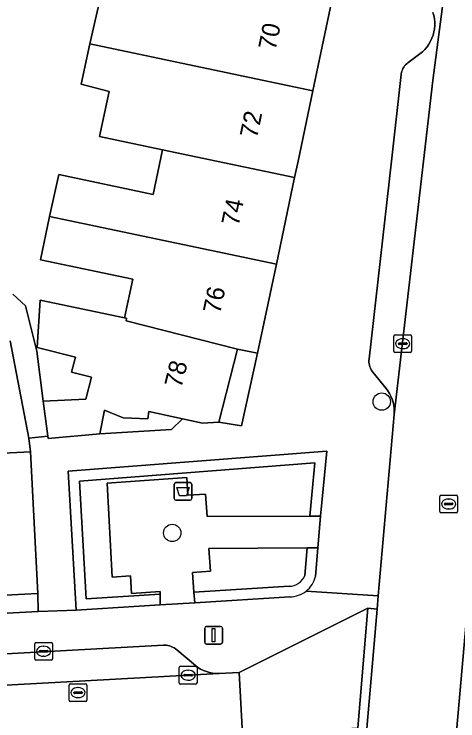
# Model space of a CAD drawing. Extents: x 160856 to 161310, y 384024 to 384878.
# Drawn here: x 161108.27 to 161133.27, y 384718.5 to 384758.27 of the extents above; entities that cross this region are included whole.
import ezdxf

# ---------------------------------------------------------------- set-up
doc = ezdxf.new("R2010")
doc.units = 0
for name, color, linetype in [('IMGEO_Afvalbak', 7, 'Continuous'), ('IMGEO_Boom', 7, 'Continuous'), ('IMGEO_Brandkraan', 7, 'Continuous'), ('IMGEO_Erf', 7, 'Continuous'), ('IMGEO_Groenvoorziening', 7, 'Continuous'), ('IMGEO_Haag', 7, 'Continuous'), ('IMGEO_Kolk', 7, 'Continuous'), ('IMGEO_Lichtmast', 7, 'Continuous'), ('IMGEO_Pand', 7, 'Continuous'), ('IMGEO_Pand_nummerreeks', 7, 'Continuous'), ('IMGEO_Parkeervlak_open', 7, 'Continuous'), ('IMGEO_Rijbaan_lokaal_open', 7, 'Continuous'), ('IMGEO_Rioolput', 7, 'Continuous'), ('IMGEO_Voetpad_open', 7, 'Continuous')]:
    doc.layers.add(name, color=color, linetype=linetype)

msp = doc.modelspace()

# ---------------------------------------------------------------- linework, layer by layer
at = {"layer": 'IMGEO_Afvalbak'}
for p, q in [((161117.389, 384731.914), (161118.179, 384731.914)), ((161118.179, 384731.914), (161117.389, 384731.914)), ((161117.289, 384731.014), (161117.289, 384731.814)), ((161117.289, 384731.814), (161117.289, 384731.014)), ((161118.279, 384731.814), (161118.279, 384731.014)), ((161118.279, 384731.014), (161118.279, 384731.814)), ((161118.179, 384730.914), (161117.389, 384730.914)), ((161117.389, 384730.914), (161118.179, 384730.914))]:
    msp.add_line(p, q, dxfattribs=at)
msp.add_lwpolyline([(161117.432, 384731.628), (161118.136, 384731.628), (161117.987, 384731.158), (161117.581, 384731.158), (161117.432, 384731.628)], dxfattribs=at)
for centre, start, end in [((161117.389, 384731.814), 90, 180), ((161117.389, 384731.814), 90, 180), ((161118.179, 384731.814), 0, 90), ((161118.179, 384731.814), 360, 90), ((161117.389, 384731.014), 180, 270), ((161117.389, 384731.014), 180, 270), ((161118.179, 384731.014), 270, 0), ((161118.179, 384731.014), 270, 0)]:
    msp.add_arc(centre, 0.1, start, end, dxfattribs=at)
at = {"layer": 'IMGEO_Boom'}
for centre in [(161128.979, 384736.468), (161117.175, 384729.078)]:
    msp.add_circle(centre, 0.489, dxfattribs=at)
at = {"layer": 'IMGEO_Brandkraan'}
for p, q in [((161109.427, 384721.993), (161109.427, 384722.845)), ((161109.502, 384722.919), (161110.354, 384722.919)), ((161110.428, 384722.845), (161110.428, 384721.993)), ((161109.686, 384722.413), (161109.686, 384722.425)), ((161110.124, 384722.376), (161109.726, 384722.376)), ((161109.729, 384722.462), (161110.127, 384722.462)), ((161109.915, 384722.699), (161109.94, 384722.699)), ((161110.17, 384722.425), (161110.17, 384722.413)), ((161109.938, 384722.139), (161109.913, 384722.139)), ((161110.354, 384721.919), (161109.502, 384721.919))]:
    msp.add_line(p, q, dxfattribs=at)
for points in [[(161109.427, 384721.993), (161109.427, 384722.845)], [(161109.502, 384722.919), (161110.354, 384722.919)], [(161110.428, 384722.845), (161110.428, 384721.993)], [(161110.354, 384721.919), (161109.502, 384721.919)]]:
    msp.add_lwpolyline(points, dxfattribs=at)
for centre, radius, start, end in [((161109.504, 384722.843), 0.0765, 91.552, 178.448), ((161109.504, 384722.843), 0.0765, 91.552, 178.448), ((161110.352, 384722.843), 0.0765, 1.552, 88.448), ((161110.352, 384722.843), 0.0765, 1.552, 88.448), ((161109.726, 384722.422), 0.0403, 85.8775, 175.7526), ((161109.723, 384722.412), 0.0366, 178.938, 274.7102), ((161110.127, 384722.419), 0.043, 264.8664, 352.4533), ((161110.131, 384722.424), 0.0386, 1.7309, 96.639), ((161109.504, 384721.995), 0.0765, 181.552, 268.448), ((161109.504, 384721.995), 0.0765, 181.552, 268.448), ((161110.352, 384721.995), 0.0765, 271.552, 358.448), ((161110.352, 384721.995), 0.0765, 271.552, 358.448)]:
    msp.add_arc(centre, radius, start, end, dxfattribs=at)
for centre, major_axis, ratio, start_param, end_param in [((161109.914, 384722.419), (-0.387, 0.002), 0.722429, 4.712389, 7.853982), ((161109.939, 384722.419), (-0.39, 0.002), 0.717154, 1.570796, 4.712389)]:
    msp.add_ellipse(centre, major_axis=major_axis, ratio=ratio, start_param=start_param, end_param=end_param, dxfattribs=at)
at = {"layer": 'IMGEO_Erf'}
for points in [[(161108.204, 384742.509), (161108.91, 384741.85), (161109.547, 384739.314), (161109.913, 384736.496), (161112.313, 384736.604), (161112.629, 384737.844), (161111.507, 384738.13), (161111.719, 384738.961), (161109.56, 384739.512), (161109.731, 384742.186), (161114.492, 384741.185), (161114.95, 384743.361), (161109.757, 384744.453), (161110.268, 384746.884), (161110.792, 384749.247), (161116.104, 384748.13), (161116.632, 384750.64), (161113.088, 384751.385), (161113.622, 384753.927), (161112.04, 384754.333), (161112.544, 384756.594), (161113.097, 384759.079)], [(161104.193, 384733.394), (161109.186, 384733.651), (161109.099, 384734.403), (161108.056, 384739.886)]]:
    msp.add_lwpolyline(points, dxfattribs=at)
for points in [[(161117.139, 384734.904), (161117.758, 384735.497), (161115.862, 384735.903), (161115.798, 384735.497), (161114.414, 384735.547), (161113.36, 384735.992), (161113.104, 384734.661)], [(161109.597, 384725.668), (161104.46, 384725.404), (161099.443, 384725.146), (161094.427, 384724.888), (161089.411, 384724.63), (161084.394, 384724.371), (161079.378, 384724.113), (161074.362, 384723.855), (161069.224, 384723.591), (161069.34, 384722.503), (161109.616, 384724.666)]]:
    msp.add_lwpolyline(points, close=True, dxfattribs=at)
at = {"layer": 'IMGEO_Groenvoorziening'}
for points in [[(161116.498, 384725.626), (161112.335, 384725.367), (161111.949, 384732), (161125.216, 384733.021), (161124.926, 384730.028), (161125.529, 384730.031), (161125.882, 384733.674), (161111.316, 384732.553), (161111.771, 384724.731), (161116.502, 384725.026)], [(161124.926, 384730.028), (161125.216, 384733.021), (161111.949, 384732), (161112.335, 384725.367), (161116.498, 384725.626), (161116.496, 384725.789), (161114.875, 384725.669), (161114.825, 384726.663), (161113.792, 384726.598), (161113.506, 384731.882), (161118, 384732.196), (161118.057, 384731.201), (161119.044, 384731.264), (161119.139, 384730)]]:
    msp.add_lwpolyline(points, close=True, dxfattribs=at)
for points in [[(161124.646, 384726.684), (161124.777, 384728.232), (161119.241, 384728.195), (161119.325, 384726.929), (161118.319, 384726.849), (161118.403, 384725.745), (161123.764, 384726.079)], [(161125.244, 384726.633), (161125.379, 384728.236), (161124.777, 384728.232), (161124.646, 384726.684)], [(161123.764, 384726.079), (161118.403, 384725.745), (161118.448, 384725.147), (161123.801, 384725.48)]]:
    msp.add_lwpolyline(points, dxfattribs=at)
for centre, radius, start, end in [((161123.771, 384727.014), 0.935, 269.5774, 339.3182), ((161123.771, 384727.014), 0.935, 269.5774, 339.3182), ((161123.789, 384726.977), 1.496, 308.5687, 346.6868), ((161123.784, 384726.982), 1.502, 270.6515, 308.593)]:
    msp.add_arc(centre, radius, start, end, dxfattribs=at)
at = {"layer": 'IMGEO_Haag'}
msp.add_lwpolyline([(161116.498, 384725.626), (161112.335, 384725.367), (161111.949, 384732), (161125.216, 384733.021), (161124.926, 384730.028), (161125.529, 384730.031), (161125.882, 384733.674), (161111.316, 384732.553), (161111.771, 384724.731), (161116.502, 384725.026)], close=True, dxfattribs=at)
for points in [[(161125.244, 384726.633), (161125.379, 384728.236), (161124.777, 384728.232), (161124.646, 384726.684)], [(161123.764, 384726.079), (161118.403, 384725.745), (161118.448, 384725.147), (161123.801, 384725.48)]]:
    msp.add_lwpolyline(points, dxfattribs=at)
for centre, radius, start, end in [((161123.771, 384727.014), 0.935, 269.5774, 339.3182), ((161123.789, 384726.977), 1.496, 308.5687, 346.6868), ((161123.784, 384726.982), 1.502, 270.6515, 308.593)]:
    msp.add_arc(centre, radius, start, end, dxfattribs=at)
at = {"layer": 'IMGEO_Kolk'}
for p, q in [((161129.663, 384739.302), (161129.663, 384740.154)), ((161129.738, 384740.228), (161130.59, 384740.228)), ((161130.151, 384740.008), (161130.176, 384740.008)), ((161130.664, 384740.154), (161130.664, 384739.302)), ((161129.922, 384739.722), (161129.922, 384739.734)), ((161130.36, 384739.685), (161129.962, 384739.685)), ((161129.965, 384739.771), (161130.363, 384739.771)), ((161130.406, 384739.734), (161130.406, 384739.722)), ((161130.59, 384739.228), (161129.738, 384739.228)), ((161130.174, 384739.448), (161130.149, 384739.448)), ((161117.648, 384721.572), (161118.5, 384721.572)), ((161117.573, 384720.646), (161117.573, 384721.498)), ((161118.061, 384721.352), (161118.086, 384721.352)), ((161118.574, 384721.498), (161118.574, 384720.646)), ((161117.832, 384721.066), (161117.832, 384721.078)), ((161118.27, 384721.029), (161117.872, 384721.029)), ((161117.875, 384721.115), (161118.273, 384721.115)), ((161118.084, 384720.792), (161118.059, 384720.792)), ((161118.316, 384721.078), (161118.316, 384721.066)), ((161118.5, 384720.572), (161117.648, 384720.572))]:
    msp.add_line(p, q, dxfattribs=at)
for points in [[(161129.663, 384739.302), (161129.663, 384740.154)], [(161129.738, 384740.228), (161130.59, 384740.228)], [(161130.664, 384740.154), (161130.664, 384739.302)], [(161130.59, 384739.228), (161129.738, 384739.228)], [(161117.648, 384721.572), (161118.5, 384721.572)], [(161117.573, 384720.646), (161117.573, 384721.498)], [(161118.574, 384721.498), (161118.574, 384720.646)], [(161118.5, 384720.572), (161117.648, 384720.572)]]:
    msp.add_lwpolyline(points, dxfattribs=at)
for centre, radius, start, end in [((161129.74, 384740.152), 0.0765, 91.552, 178.448), ((161129.74, 384740.152), 0.0765, 91.552, 178.448), ((161130.588, 384740.152), 0.0765, 1.552, 88.448), ((161130.588, 384740.152), 0.0765, 1.552, 88.448), ((161129.962, 384739.731), 0.0403, 85.8775, 175.7526), ((161129.959, 384739.721), 0.0366, 178.938, 274.7102), ((161130.363, 384739.728), 0.043, 264.8664, 352.4533), ((161130.367, 384739.733), 0.0386, 1.7309, 96.639), ((161129.74, 384739.304), 0.0765, 181.552, 268.448), ((161129.74, 384739.304), 0.0765, 181.552, 268.448), ((161130.588, 384739.304), 0.0765, 271.552, 358.448), ((161130.588, 384739.304), 0.0765, 271.552, 358.448), ((161117.65, 384721.496), 0.0765, 91.552, 178.448), ((161117.65, 384721.496), 0.0765, 91.552, 178.448), ((161118.498, 384721.496), 0.0765, 1.552, 88.448), ((161118.498, 384721.496), 0.0765, 1.552, 88.448), ((161117.872, 384721.075), 0.0403, 85.8775, 175.7526), ((161117.869, 384721.065), 0.0366, 178.938, 274.7102), ((161118.273, 384721.072), 0.043, 264.8664, 352.4533), ((161118.277, 384721.077), 0.0386, 1.7309, 96.639), ((161117.65, 384720.648), 0.0765, 181.552, 268.448), ((161117.65, 384720.648), 0.0765, 181.552, 268.448), ((161118.498, 384720.648), 0.0765, 271.552, 358.448), ((161118.498, 384720.648), 0.0765, 271.552, 358.448)]:
    msp.add_arc(centre, radius, start, end, dxfattribs=at)
for centre, major_axis, ratio, start_param, end_param in [((161130.15, 384739.728), (-0.387, 0.002), 0.722429, 4.712389, 7.853982), ((161130.175, 384739.728), (-0.39, 0.002), 0.717154, 1.570796, 4.712389), ((161118.06, 384721.072), (-0.387, 0.002), 0.722429, 4.712389, 7.853982), ((161118.085, 384721.072), (-0.39, 0.002), 0.717154, 1.570796, 4.712389)]:
    msp.add_ellipse(centre, major_axis=major_axis, ratio=ratio, start_param=start_param, end_param=end_param, dxfattribs=at)
at = {"layer": 'IMGEO_Lichtmast'}
for p, q in [((161119.01, 384722.919), (161119.01, 384723.719)), ((161119.01, 384723.719), (161119.01, 384722.919)), ((161119.11, 384723.819), (161119.9, 384723.819)), ((161119.9, 384723.819), (161119.11, 384723.819)), ((161120, 384723.719), (161120, 384722.919)), ((161120, 384722.919), (161120, 384723.719)), ((161119.9, 384722.819), (161119.11, 384722.819)), ((161119.11, 384722.819), (161119.9, 384722.819))]:
    msp.add_line(p, q, dxfattribs=at)
msp.add_lwpolyline([(161119.43, 384723.694), (161119.58, 384723.694), (161119.58, 384722.944), (161119.43, 384722.944), (161119.43, 384723.694)], dxfattribs=at)
for centre, start, end in [((161119.11, 384723.719), 90, 180), ((161119.11, 384723.719), 90, 180), ((161119.9, 384723.719), 0, 90), ((161119.9, 384723.719), 360, 90), ((161119.11, 384722.919), 180, 270), ((161119.11, 384722.919), 180, 270), ((161119.9, 384722.919), 270, 0), ((161119.9, 384722.919), 270, 0)]:
    msp.add_arc(centre, 0.1, start, end, dxfattribs=at)
at = {"layer": 'IMGEO_Pand'}
for points in [[(161114.927, 384761.077), (161114.448, 384758.795), (161113.097, 384759.079), (161112.544, 384756.594), (161125.094, 384753.955), (161126.145, 384758.952), (161125.127, 384759.166), (161118.763, 384760.502), (161118.728, 384760.335), (161117.644, 384760.568)], [(161124.069, 384749.076), (161124.263, 384750), (161125.094, 384753.955), (161112.544, 384756.594), (161112.04, 384754.333), (161113.622, 384753.927), (161113.088, 384751.385), (161116.632, 384750.64), (161119.677, 384750)], [(161124.069, 384749.076), (161119.677, 384750), (161116.632, 384750.64), (161116.104, 384748.13), (161110.792, 384749.247), (161110.268, 384746.884), (161123.043, 384744.198)], [(161123.043, 384744.198), (161110.268, 384746.884), (161109.757, 384744.453), (161114.95, 384743.361), (161114.492, 384741.185), (161114.61, 384741.16), (161114.574, 384741.018), (161120.854, 384739.425), (161121.99, 384739.186)], [(161120.854, 384739.425), (161114.574, 384741.018), (161114.61, 384741.16), (161114.492, 384741.185), (161109.731, 384742.186), (161109.56, 384739.512), (161111.719, 384738.961), (161111.507, 384738.13), (161112.629, 384737.844), (161112.313, 384736.604), (161109.913, 384736.496), (161110.169, 384734.526), (161110.186, 384734.397), (161113.104, 384734.661), (161113.36, 384735.992), (161114.414, 384735.547), (161115.798, 384735.497), (161115.862, 384735.903), (161117.758, 384735.497), (161118.878, 384735.258), (161119.811, 384735.306)], [(161104.46, 384725.404), (161109.597, 384725.668), (161109.186, 384733.651), (161104.193, 384733.394), (161104.049, 384733.386)]]:
    msp.add_lwpolyline(points, close=True, dxfattribs=at)
at = {"layer": 'IMGEO_Parkeervlak_open'}
for points in [[(161131.858, 384758.372), (161131.91, 384758.193), (161131.945, 384758.011), (161131.964, 384757.826), (161131.966, 384757.64), (161131.951, 384757.454), (161131.921, 384757.271), (161131.873, 384757.091), (161131.81, 384756.916), (161131.732, 384756.747), (161131.639, 384756.586), (161131.532, 384756.434), (161131.411, 384756.293), (161131.279, 384756.162), (161131.135, 384756.044), (161130.45, 384755.539), (161130.385, 384755.486), (161130.324, 384755.428), (161130.269, 384755.365), (161130.22, 384755.297), (161130.178, 384755.224), (161130.142, 384755.149), (161130.112, 384755.07), (161130.09, 384754.989), (161130.075, 384754.906), (161130.073, 384754.886), (161129.521, 384750), (161128.265, 384738.873), (161128.259, 384738.783), (161128.261, 384738.693), (161128.271, 384738.603), (161128.289, 384738.515), (161128.315, 384738.428), (161128.348, 384738.345), (161128.389, 384738.264), (161128.437, 384738.188), (161128.478, 384738.132), (161129.232, 384737.201), (161129.326, 384737.078), (161129.421, 384736.931), (161129.502, 384736.775), (161129.569, 384736.613), (161129.621, 384736.445), (161129.658, 384736.274), (161129.68, 384736.1), (161129.686, 384735.924), (161129.676, 384735.749), (161131.333, 384750), (161131.86, 384754.533), (161132.507, 384759.586)], [(161134.909, 384737.229), (161132.216, 384706.852), (161132.281, 384707.27), (161132.384, 384707.682), (161132.523, 384708.084), (161132.697, 384708.472), (161132.905, 384708.842), (161133.8, 384709.628), (161133.869, 384709.695), (161133.932, 384709.768), (161133.988, 384709.846), (161134.038, 384709.929), (161134.079, 384710.016), (161134.112, 384710.106), (161134.138, 384710.199), (161134.155, 384710.293), (161134.158, 384710.321), (161136.264, 384730.269)], [(161071.831, 384718.54), (161119.802, 384721.162), (161119.624, 384721.166), (161119.446, 384721.186), (161119.271, 384721.222), (161119.1, 384721.273), (161118.934, 384721.339), (161118.775, 384721.42), (161118.623, 384721.515), (161118.481, 384721.623), (161117.439, 384722.493), (161117.363, 384722.553), (161117.283, 384722.606), (161117.198, 384722.652), (161117.109, 384722.689), (161117.017, 384722.719), (161116.923, 384722.741), (161116.827, 384722.754), (161116.731, 384722.758), (161116.687, 384722.757), (161074.676, 384720.464)]]:
    msp.add_lwpolyline(points, dxfattribs=at)
at = {"layer": 'IMGEO_Rijbaan_lokaal_open'}
for points in [[(161144.864, 384818.229), (161132.813, 384761.681), (161132.507, 384759.586), (161131.86, 384754.533), (161131.333, 384750), (161129.676, 384735.749), (161128.787, 384725.541), (161128.722, 384724.796), (161128.062, 384717.217)], [(161132.216, 384706.852), (161134.909, 384737.229), (161134.947, 384737.659), (161135.071, 384738.699), (161137.359, 384757.16), (161137.441, 384757.872), (161138.061, 384762.728), (161147.796, 384807.819)]]:
    msp.add_lwpolyline(points, dxfattribs=at)
for points in [[(161121.139, 384717.759), (161127.641, 384718.106), (161128.202, 384724.839), (161120.943, 384721.23)], [(161071.831, 384718.54), (161072.03, 384715.044), (161101.964, 384716.699), (161108.035, 384717.035), (161121.139, 384717.759), (161120.943, 384721.23), (161119.828, 384721.163), (161119.802, 384721.162)]]:
    msp.add_lwpolyline(points, close=True, dxfattribs=at)
at = {"layer": 'IMGEO_Rioolput'}
for p, q in [((161132.249, 384730.28), (161132.249, 384731.132)), ((161132.324, 384731.206), (161133.176, 384731.206)), ((161133.25, 384731.132), (161133.25, 384730.28)), ((161132.551, 384730.749), (161132.949, 384730.749)), ((161132.737, 384730.986), (161132.762, 384730.986)), ((161132.508, 384730.7), (161132.508, 384730.712)), ((161132.946, 384730.663), (161132.548, 384730.663)), ((161132.76, 384730.426), (161132.735, 384730.426)), ((161132.992, 384730.712), (161132.992, 384730.7)), ((161133.176, 384730.206), (161132.324, 384730.206)), ((161111.371, 384719.666), (161111.371, 384720.518)), ((161111.446, 384720.592), (161112.298, 384720.592)), ((161112.372, 384720.518), (161112.372, 384719.666)), ((161111.63, 384720.086), (161111.63, 384720.098)), ((161112.068, 384720.049), (161111.67, 384720.049)), ((161111.673, 384720.135), (161112.071, 384720.135)), ((161111.859, 384720.372), (161111.884, 384720.372)), ((161112.114, 384720.098), (161112.114, 384720.086)), ((161112.298, 384719.592), (161111.446, 384719.592)), ((161111.882, 384719.812), (161111.857, 384719.812))]:
    msp.add_line(p, q, dxfattribs=at)
for points in [[(161132.249, 384730.28), (161132.249, 384731.132)], [(161132.324, 384731.206), (161133.176, 384731.206)], [(161133.25, 384731.132), (161133.25, 384730.28)], [(161133.176, 384730.206), (161132.324, 384730.206)], [(161111.371, 384719.666), (161111.371, 384720.518)], [(161111.446, 384720.592), (161112.298, 384720.592)], [(161112.372, 384720.518), (161112.372, 384719.666)], [(161112.298, 384719.592), (161111.446, 384719.592)]]:
    msp.add_lwpolyline(points, dxfattribs=at)
for centre, radius, start, end in [((161132.326, 384731.13), 0.0765, 91.552, 178.448), ((161132.326, 384731.13), 0.0765, 91.552, 178.448), ((161133.174, 384731.13), 0.0765, 1.552, 88.448), ((161133.174, 384731.13), 0.0765, 1.552, 88.448), ((161132.548, 384730.709), 0.0403, 85.8775, 175.7526), ((161132.953, 384730.711), 0.0386, 1.7309, 96.639), ((161132.545, 384730.699), 0.0366, 178.938, 274.7102), ((161132.949, 384730.706), 0.043, 264.8664, 352.4533), ((161132.326, 384730.282), 0.0765, 181.552, 268.448), ((161132.326, 384730.282), 0.0765, 181.552, 268.448), ((161133.174, 384730.282), 0.0765, 271.552, 358.448), ((161133.174, 384730.282), 0.0765, 271.552, 358.448), ((161111.448, 384720.516), 0.0765, 91.552, 178.448), ((161111.448, 384720.516), 0.0765, 91.552, 178.448), ((161112.296, 384720.516), 0.0765, 1.552, 88.448), ((161112.296, 384720.516), 0.0765, 1.552, 88.448), ((161111.67, 384720.095), 0.0403, 85.8775, 175.7526), ((161111.667, 384720.085), 0.0366, 178.938, 274.7102), ((161112.071, 384720.092), 0.043, 264.8664, 352.4533), ((161112.075, 384720.097), 0.0386, 1.7309, 96.639), ((161111.448, 384719.668), 0.0765, 181.552, 268.448), ((161111.448, 384719.668), 0.0765, 181.552, 268.448), ((161112.296, 384719.668), 0.0765, 271.552, 358.448), ((161112.296, 384719.668), 0.0765, 271.552, 358.448)]:
    msp.add_arc(centre, radius, start, end, dxfattribs=at)
for centre, major_axis, ratio, start_param, end_param in [((161132.736, 384730.706), (-0.387, 0.002), 0.722429, 4.712389, 7.853982), ((161132.761, 384730.706), (-0.39, 0.002), 0.717154, 1.570796, 4.712389), ((161111.858, 384720.092), (-0.387, 0.002), 0.722429, 4.712389, 7.853982), ((161111.883, 384720.092), (-0.39, 0.002), 0.717154, 1.570796, 4.712389)]:
    msp.add_ellipse(centre, major_axis=major_axis, ratio=ratio, start_param=start_param, end_param=end_param, dxfattribs=at)
at = {"layer": 'IMGEO_Voetpad_open'}
for points in [[(161126.145, 384758.952), (161125.094, 384753.955), (161124.263, 384750), (161124.069, 384749.076), (161123.043, 384744.198), (161121.99, 384739.186), (161121.088, 384735.109), (161119.811, 384735.306), (161118.878, 384735.258), (161117.758, 384735.497), (161117.139, 384734.904), (161113.104, 384734.661), (161110.186, 384734.397), (161110.169, 384734.526), (161109.099, 384734.403), (161109.186, 384733.651), (161109.597, 384725.668), (161109.616, 384724.666), (161111.771, 384724.731), (161111.316, 384732.553), (161125.882, 384733.674), (161125.529, 384730.031), (161125.379, 384728.236), (161125.244, 384726.633)], [(161130.073, 384754.886), (161130.075, 384754.906), (161130.09, 384754.989), (161130.112, 384755.07), (161130.142, 384755.149), (161130.178, 384755.224), (161130.22, 384755.297), (161130.269, 384755.365), (161130.324, 384755.428), (161130.385, 384755.486), (161130.45, 384755.539), (161131.135, 384756.044), (161131.279, 384756.162), (161131.411, 384756.293), (161131.532, 384756.434), (161131.639, 384756.586), (161131.732, 384756.747), (161131.81, 384756.916), (161131.873, 384757.091), (161131.921, 384757.271), (161131.951, 384757.454), (161131.966, 384757.64), (161131.964, 384757.826), (161131.945, 384758.011), (161131.91, 384758.193), (161131.858, 384758.372)], [(161124.721, 384725.808), (161128.787, 384725.541), (161129.676, 384735.749), (161129.686, 384735.924), (161129.68, 384736.1), (161129.658, 384736.274), (161129.621, 384736.445), (161129.569, 384736.613), (161129.502, 384736.775), (161129.421, 384736.931), (161129.326, 384737.078), (161129.232, 384737.201), (161128.478, 384738.132), (161128.437, 384738.188), (161128.389, 384738.264), (161128.348, 384738.345), (161128.315, 384738.428), (161128.289, 384738.515), (161128.271, 384738.603), (161128.261, 384738.693), (161128.259, 384738.783), (161128.265, 384738.873), (161129.521, 384750), (161130.073, 384754.886)], [(161108.056, 384739.886), (161109.099, 384734.403), (161110.169, 384734.526), (161109.913, 384736.496), (161109.547, 384739.314), (161108.91, 384741.85), (161108.204, 384742.509)], [(161116.687, 384722.757), (161116.731, 384722.758), (161116.827, 384722.754), (161116.923, 384722.741), (161117.017, 384722.719), (161117.109, 384722.689), (161117.198, 384722.652), (161117.283, 384722.606), (161117.363, 384722.553), (161117.439, 384722.493), (161118.481, 384721.623), (161118.623, 384721.515), (161118.775, 384721.42), (161118.934, 384721.339), (161119.1, 384721.273), (161119.271, 384721.222), (161119.446, 384721.186), (161119.624, 384721.166), (161119.802, 384721.162), (161119.828, 384721.163), (161120.943, 384721.23), (161128.202, 384724.839), (161128.722, 384724.796), (161128.787, 384725.541), (161124.721, 384725.808)], [(161123.801, 384725.48), (161118.448, 384725.147), (161116.502, 384725.026), (161111.771, 384724.731), (161109.616, 384724.666), (161069.34, 384722.503)], [(161074.676, 384720.464), (161116.687, 384722.757)]]:
    msp.add_lwpolyline(points, dxfattribs=at)
for points in [[(161121.088, 384735.109), (161121.99, 384739.186), (161120.854, 384739.425), (161119.811, 384735.306)], [(161125.529, 384730.031), (161124.926, 384730.028), (161119.139, 384730), (161119.044, 384731.264), (161118.057, 384731.201), (161118, 384732.196), (161113.506, 384731.882), (161113.792, 384726.598), (161114.825, 384726.663), (161114.875, 384725.669), (161116.496, 384725.789), (161116.498, 384725.626), (161116.502, 384725.026), (161118.448, 384725.147), (161118.403, 384725.745), (161118.319, 384726.849), (161119.325, 384726.929), (161119.241, 384728.195), (161124.777, 384728.232), (161125.379, 384728.236)], [(161128.722, 384724.796), (161128.202, 384724.839), (161127.641, 384718.106), (161127.57, 384717.257), (161128.062, 384717.217)]]:
    msp.add_lwpolyline(points, close=True, dxfattribs=at)
for centre, radius, start, end in [((161123.789, 384726.977), 1.496, 308.5687, 346.6868), ((161123.784, 384726.982), 1.502, 270.6515, 308.593)]:
    msp.add_arc(centre, radius, start, end, dxfattribs=at)

# ---------------------------------------------------------------- texts
at = {"layer": 'IMGEO_Pand_nummerreeks'}
for s, rotation, p in [('70', 78.1287, (161122.991, 384756.194)), ('72', 78.1287, (161121.95, 384751.246)), ('74', 78.1285, (161120.912, 384746.309)), ('76', 78.1287, (161119.873, 384741.366)), ('78', 75.7909, (161117.688, 384737.185))]:
    msp.add_text(s, height=1, rotation=rotation, dxfattribs=at).set_placement(p)

doc.saveas('drawing.dxf')
